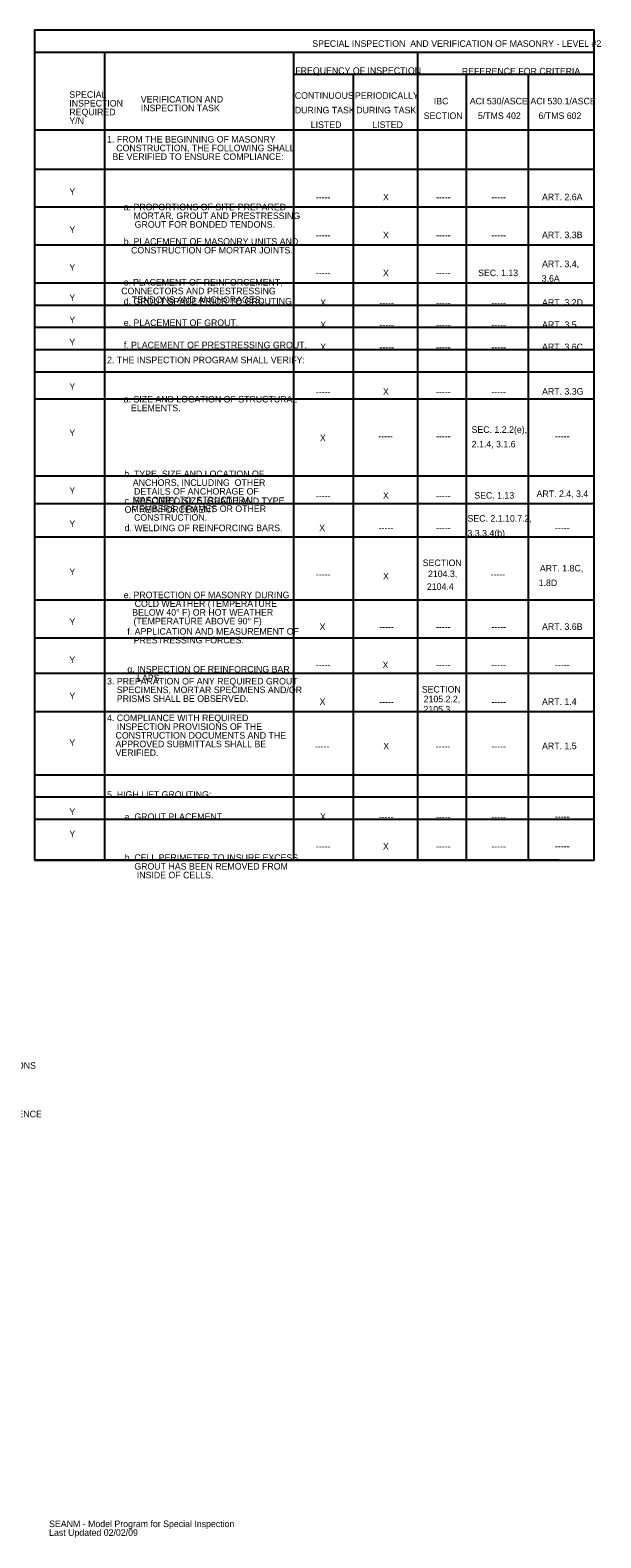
# Model space of a CAD drawing. Extents: x 2632118 to 2632142.4, y 1706724.1 to 1706788.4.
# Drawn here: x 2632134.87 to 2632142.12, y 1706748.63 to 1706767.77 of the extents above; entities that cross this region are included whole.
import ezdxf

# ---------------------------------------------------------------- set-up
doc = ezdxf.new("R2010")
doc.units = 0
doc.layers.add('Default', color=7, linetype='Continuous')

msp = doc.modelspace()

# ---------------------------------------------------------------- linework, layer by layer
at = {"layer": 'Default'}
for p, q in [((2632135.811, 1706767.493), (2632135.811, 1706757.234)), ((2632138.214, 1706767.493), (2632138.214, 1706757.234)), ((2632139.787, 1706767.493), (2632139.787, 1706757.234)), ((2632142.033, 1706767.211), (2632138.214, 1706767.211)), ((2632138.971, 1706767.211), (2632138.971, 1706757.234)), ((2632140.408, 1706767.211), (2632140.408, 1706757.234)), ((2632141.195, 1706767.211), (2632141.195, 1706757.234)), ((2632142.033, 1706766.505), (2632134.922, 1706766.505)), ((2632142.033, 1706766.007), (2632134.922, 1706766.007)), ((2632142.033, 1706765.525), (2632134.922, 1706765.525)), ((2632142.033, 1706765.043), (2632134.922, 1706765.043)), ((2632142.033, 1706764.561), (2632134.922, 1706764.561)), ((2632142.033, 1706764.279), (2632134.922, 1706764.279)), ((2632142.033, 1706763.997), (2632134.922, 1706763.997)), ((2632142.033, 1706763.714), (2632134.922, 1706763.714)), ((2632142.033, 1706763.432), (2632134.922, 1706763.432)), ((2632142.033, 1706763.088), (2632134.922, 1706763.088)), ((2632142.033, 1706762.112), (2632134.922, 1706762.112)), ((2632142.033, 1706761.761), (2632134.922, 1706761.761)), ((2632142.033, 1706761.338), (2632134.922, 1706761.338)), ((2632142.033, 1706760.538), (2632134.922, 1706760.538)), ((2632142.033, 1706760.055), (2632134.922, 1706760.055)), ((2632142.033, 1706759.603), (2632134.922, 1706759.603)), ((2632142.033, 1706759.119), (2632134.922, 1706759.119)), ((2632142.033, 1706758.315), (2632134.922, 1706758.315)), ((2632142.033, 1706758.033), (2632134.922, 1706758.033)), ((2632142.033, 1706757.751), (2632134.922, 1706757.751)), ((2632141.588, 1706757.234), (2632134.922, 1706757.234))]:
    msp.add_line(p, q, dxfattribs=at)
msp.add_lwpolyline([(2632134.922, 1706757.234), (2632142.033, 1706757.234), (2632142.033, 1706767.775), (2632134.922, 1706767.775)], close=True, dxfattribs=at)
msp.add_lwpolyline([(2632142.033, 1706767.493), (2632134.922, 1706767.493)], dxfattribs=at)

# ---------------------------------------------------------------- texts
for s, height, p in [('SPECIAL INSPECTION  AND VERIFICATION OF MASONRY - LEVEL #2', 0.08333, (2632138.452, 1706767.563)), ('FREQUENCY OF INSPECTION ', 0.08333, (2632138.237, 1706767.219)), ('REFERENCE FOR CRITERIA', 0.08333, (2632140.352, 1706767.213)), ('SPECIAL ', 0.0833, (2632135.366, 1706766.916)), ('INSPECTION ', 0.08333, (2632135.366, 1706766.805)), ('VERIFICATION AND ', 0.08333, (2632136.274, 1706766.856)), ('INSPECTION TASK ', 0.08333, (2632136.274, 1706766.745)), ('CONTINUOUS', 0.0833, (2632138.23, 1706766.903)), ('PERIODICALLY', 0.08333, (2632138.994, 1706766.903)), ('IBC', 0.0833, (2632139.996, 1706766.832)), ('ACI 530/ASCE', 0.08333, (2632140.453, 1706766.832)), ('ACI 530.1/ASCE', 0.08333, (2632141.223, 1706766.832)), ('Y/N', 0.0833, (2632135.366, 1706766.583)), ('REQUIRED', 0.0833, (2632135.366, 1706766.694)), ('DURING TASK', 0.08333, (2632138.23, 1706766.718)), ('DURING TASK', 0.08333, (2632139.011, 1706766.718)), ('SECTION', 0.0833, (2632139.867, 1706766.647)), ('5/TMS 402', 0.0833, (2632140.556, 1706766.647)), ('6/TMS 602', 0.0833, (2632141.326, 1706766.647)), ('LISTED', 0.0833, (2632138.433, 1706766.533)), ('LISTED', 0.0833, (2632139.214, 1706766.533)), ('1. FROM THE BEGINNING OF MASONRY ', 0.08333, (2632135.845, 1706766.348)), ('   CONSTRUCTION, THE FOLLOWING SHALL ', 0.08333, (2632135.869, 1706766.237)), ('   BE VERIFIED TO ENSURE COMPLIANCE: ', 0.08333, (2632135.821, 1706766.126)), ('Y', 0.0833, (2632135.366, 1706765.683)), ('X', 0.0833, (2632139.35, 1706765.613)), ('ART. 2.6A', 0.0833, (2632141.371, 1706765.615)), ('a. PROPORTIONS OF SITE-PREPARED ', 0.08333, (2632136.057, 1706765.487)), ('-----', 0.0833, (2632138.498, 1706765.613)), ('-----', 0.0833, (2632140.025, 1706765.613)), ('-----', 0.0833, (2632140.727, 1706765.613)), ('    MORTAR, GROUT AND PRESTRESSING ', 0.08333, (2632136.057, 1706765.376)), ('    GROUT FOR BONDED TENDONS.', 0.08333, (2632136.072, 1706765.266)), ('Y', 0.0833, (2632135.366, 1706765.201)), ('b. PLACEMENT OF MASONRY UNITS AND ', 0.08333, (2632136.057, 1706765.05)), ('-----', 0.0833, (2632138.498, 1706765.131)), ('X', 0.0833, (2632139.35, 1706765.131)), ('-----', 0.0833, (2632140.025, 1706765.131)), ('-----', 0.0833, (2632140.727, 1706765.131)), ('ART. 3.3B', 0.0833, (2632141.371, 1706765.133)), ('   CONSTRUCTION OF MORTAR JOINTS.', 0.08333, (2632136.057, 1706764.939)), ('Y', 0.0833, (2632135.366, 1706764.719)), ('X', 0.0833, (2632139.35, 1706764.649)), ('SEC. 1.13', 0.0833, (2632140.559, 1706764.651)), ('ART. 3.4,', 0.0833, (2632141.371, 1706764.765)), ('c. PLACEMENT OF REINFORCEMENT, ', 0.08333, (2632136.057, 1706764.532)), ('-----', 0.0833, (2632138.498, 1706764.649)), ('-----', 0.0833, (2632140.025, 1706764.649)), ('3.6A', 0.0833, (2632141.366, 1706764.58)), ('Y', 0.0833, (2632135.366, 1706764.337)), ('   CONNECTORS AND PRESTRESSING ', 0.08333, (2632135.932, 1706764.421)), ('d. GROUT SPACE PRIOR TO GROUTING.', 0.08333, (2632136.057, 1706764.291)), ('   TENDONS AND ANCHORAGES.', 0.08333, (2632136.068, 1706764.31)), ('X', 0.0833, (2632138.553, 1706764.273)), ('ART. 3.2D', 0.0833, (2632141.371, 1706764.275)), ('-----', 0.0833, (2632139.305, 1706764.273)), ('-----', 0.0833, (2632140.025, 1706764.273)), ('-----', 0.0833, (2632140.727, 1706764.273)), ('Y', 0.0833, (2632135.366, 1706764.054)), ('e. PLACEMENT OF GROUT.', 0.08333, (2632136.057, 1706764.018)), ('X', 0.0833, (2632138.553, 1706763.991)), ('-----', 0.0833, (2632139.305, 1706763.991)), ('-----', 0.0833, (2632140.025, 1706763.991)), ('-----', 0.0833, (2632140.727, 1706763.991)), ('ART. 3.5', 0.0833, (2632141.371, 1706763.993)), ('Y', 0.0833, (2632135.366, 1706763.772)), ('f. PLACEMENT OF PRESTRESSING GROUT.', 0.08333, (2632136.057, 1706763.735)), ('X', 0.0833, (2632138.553, 1706763.709)), ('ART. 3.6C', 0.0833, (2632141.371, 1706763.711)), ('2. THE INSPECTION PROGRAM SHALL VERIFY:', 0.08333, (2632135.845, 1706763.545)), ('-----', 0.0833, (2632139.305, 1706763.709)), ('-----', 0.0833, (2632140.025, 1706763.709)), ('-----', 0.0833, (2632140.727, 1706763.709)), ('Y', 0.0833, (2632135.366, 1706763.208)), ('X', 0.0833, (2632139.35, 1706763.144)), ('ART. 3.3G', 0.0833, (2632141.371, 1706763.146)), ('a. SIZE AND LOCATION OF STRUCTURAL ', 0.08333, (2632136.057, 1706763.047)), ('    ELEMENTS.', 0.08333, (2632136.025, 1706762.936)), ('-----', 0.0833, (2632138.498, 1706763.144)), ('-----', 0.0833, (2632140.025, 1706763.144)), ('-----', 0.0833, (2632140.727, 1706763.144)), ('Y', 0.0833, (2632135.366, 1706762.619)), ('X', 0.0833, (2632138.549, 1706762.554)), ('-----', 0.0833, (2632139.29, 1706762.578)), ('-----', 0.0833, (2632140.025, 1706762.578)), ('SEC. 1.2.2(e),', 0.08333, (2632140.475, 1706762.661)), ('-----', 0.0833, (2632141.535, 1706762.578)), ('2.1.4, 3.1.6', 0.08333, (2632140.477, 1706762.476)), ('b. TYPE, SIZE AND LOCATION OF ', 0.08333, (2632136.064, 1706762.099)), ('    ANCHORS, INCLUDING  OTHER ', 0.08333, (2632136.048, 1706761.988)), ('Y', 0.0833, (2632135.366, 1706761.888)), ('    MASONRY TO  STRUCTURAL', 0.08333, (2632136.048, 1706761.766)), ('    DETAILS OF ANCHORAGE OF ', 0.08333, (2632136.064, 1706761.877)), ('-----', 0.0833, (2632138.498, 1706761.824)), ('X', 0.0833, (2632139.35, 1706761.824)), ('-----', 0.0833, (2632140.025, 1706761.824)), ('SEC. 1.13', 0.0833, (2632140.51, 1706761.826)), ('ART. 2.4, 3.4', 0.08333, (2632141.301, 1706761.846)), ('c. SPECIFIED SIZE, GRADE AND TYPE ', 0.08333, (2632136.068, 1706761.757)), ('OF REINFORCEMENT', 0.08333, (2632136.068, 1706761.646)), ('    MEMBERS, FRAMES OR OTHER', 0.08333, (2632136.032, 1706761.656)), ('Y', 0.0833, (2632135.366, 1706761.466)), ('d. WELDING OF REINFORCING BARS.', 0.08333, (2632136.068, 1706761.412)), ('    CONSTRUCTION.', 0.08333, (2632136.064, 1706761.545)), ('X', 0.0833, (2632138.541, 1706761.412)), ('SEC. 2.1.10.7.2,', 0.08333, (2632140.424, 1706761.533)), ('-----', 0.0833, (2632139.296, 1706761.412)), ('-----', 0.0833, (2632140.025, 1706761.412)), ('3.3.3.4(b)', 0.0833, (2632140.424, 1706761.345)), ('-----', 0.0833, (2632141.535, 1706761.412)), ('Y', 0.0833, (2632135.366, 1706760.855)), ('SECTION', 0.0833, (2632139.855, 1706760.969)), ('2104.3,', 0.0833, (2632139.922, 1706760.829)), ('ART. 1.8C,', 0.0833, (2632141.343, 1706760.901)), ('-----', 0.0833, (2632138.498, 1706760.824)), ('X', 0.0833, (2632139.35, 1706760.8)), ('2104.4', 0.0833, (2632139.908, 1706760.667)), ('-----', 0.0833, (2632140.717, 1706760.824)), ('1.8D', 0.0833, (2632141.328, 1706760.715)), ('e. PROTECTION OF MASONRY DURING ', 0.08333, (2632136.057, 1706760.561)), ('    COLD WEATHER (TEMPERATURE ', 0.08333, (2632136.072, 1706760.451)), ('    BELOW 40%%d F) OR HOT WEATHER', 0.08333, (2632136.041, 1706760.34)), ('    (TEMPERATURE ABOVE 90%%d F)', 0.08333, (2632136.057, 1706760.229)), ('Y', 0.0833, (2632135.366, 1706760.221)), ('f. APPLICATION AND MEASUREMENT OF ', 0.08333, (2632136.103, 1706760.098)), ('X', 0.0833, (2632138.545, 1706760.157)), ('-----', 0.0833, (2632139.302, 1706760.157)), ('-----', 0.0833, (2632140.025, 1706760.157)), ('-----', 0.0833, (2632140.727, 1706760.157)), ('ART. 3.6B', 0.0833, (2632141.371, 1706760.159)), ('   PRESTRESSING FORCES.', 0.08333, (2632136.091, 1706759.987)), ('Y', 0.0833, (2632135.366, 1706759.738)), ('X', 0.0833, (2632139.345, 1706759.673)), ('3. PREPARATION OF ANY REQUIRED GROUT ', 0.08333, (2632135.845, 1706759.466)), ('g. INSPECTION OF REINFORCING BAR ', 0.08333, (2632136.103, 1706759.618)), ('    LAPS.', 0.0833, (2632136.103, 1706759.507)), ('-----', 0.0833, (2632138.498, 1706759.673)), ('-----', 0.0833, (2632140.025, 1706759.673)), ('-----', 0.0833, (2632140.727, 1706759.673)), ('-----', 0.0833, (2632141.535, 1706759.676)), ('Y', 0.0833, (2632135.366, 1706759.278)), ('    SPECIMENS, MORTAR SPECIMENS AND/OR ', 0.08333, (2632135.845, 1706759.356)), ('SECTION', 0.0833, (2632139.843, 1706759.363)), ('    PRISMS SHALL BE OBSERVED.', 0.08333, (2632135.845, 1706759.245)), ('X', 0.0833, (2632138.545, 1706759.205)), ('-----', 0.0833, (2632139.302, 1706759.205)), ('2105.3', 0.0833, (2632139.865, 1706759.11)), ('2105.2.2,', 0.0833, (2632139.867, 1706759.239)), ('-----', 0.0833, (2632140.727, 1706759.205)), ('ART. 1.4', 0.0833, (2632141.371, 1706759.206)), ('4. COMPLIANCE WITH REQUIRED ', 0.08333, (2632135.845, 1706759)), ('    CONSTRUCTION DOCUMENTS AND THE ', 0.08333, (2632135.829, 1706758.778)), ('    INSPECTION PROVISIONS OF THE ', 0.08333, (2632135.845, 1706758.889)), ('Y', 0.0833, (2632135.366, 1706758.684)), ('    APPROVED SUBMITTALS SHALL BE ', 0.08333, (2632135.829, 1706758.668)), ('    VERIFIED.', 0.08333, (2632135.829, 1706758.557)), ('-----', 0.0833, (2632138.484, 1706758.641)), ('X', 0.0833, (2632139.354, 1706758.641)), ('-----', 0.0833, (2632140.019, 1706758.641)), ('-----', 0.0833, (2632140.727, 1706758.641)), ('ART. 1.5', 0.0833, (2632141.371, 1706758.643)), ('5. HIGH LIFT GROUTING:', 0.08333, (2632135.845, 1706758.027)), ('Y', 0.0833, (2632135.366, 1706757.808)), ('a. GROUT PLACEMENT.', 0.08333, (2632136.068, 1706757.745)), ('X', 0.0833, (2632138.551, 1706757.745)), ('-----', 0.0833, (2632139.297, 1706757.745)), ('-----', 0.0833, (2632140.025, 1706757.745)), ('-----', 0.0833, (2632140.727, 1706757.745)), ('-----', 0.0833, (2632141.535, 1706757.748)), ('Y', 0.0833, (2632135.366, 1706757.526)), ('X', 0.0833, (2632139.35, 1706757.369)), ('b. CELL PERIMETER TO INSURE EXCESS ', 0.08333, (2632136.068, 1706757.226)), ('-----', 0.0833, (2632138.498, 1706757.369)), ('-----', 0.0833, (2632140.025, 1706757.369)), ('-----', 0.0833, (2632140.727, 1706757.369)), ('-----', 0.0833, (2632141.535, 1706757.372)), ('    GROUT HAS BEEN REMOVED FROM ', 0.08333, (2632136.068, 1706757.115)), ('    INSIDE OF CELLS.', 0.08333, (2632136.099, 1706757.004)), ('SPECIAL INSPECTION AND VERIFICATION OF PILE FOUNDATIONS', 0.08333, (2632131.381, 1706754.585)), ('REFERENCE', 0.0833, (2632134.33, 1706753.969)), ('SEANM - Model Program for Special Inspection ', 0.08333, (2632135.109, 1706748.765)), ('Last Updated 02/02/09', 0.08333, (2632135.109, 1706748.654))]:
    msp.add_text(s, height=height, dxfattribs=at).set_placement(p)

doc.saveas('drawing.dxf')
